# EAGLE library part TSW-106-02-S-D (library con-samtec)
THROUGH-HOLE .025" SQ POST HEADER Source: Samtec TSW.pdf
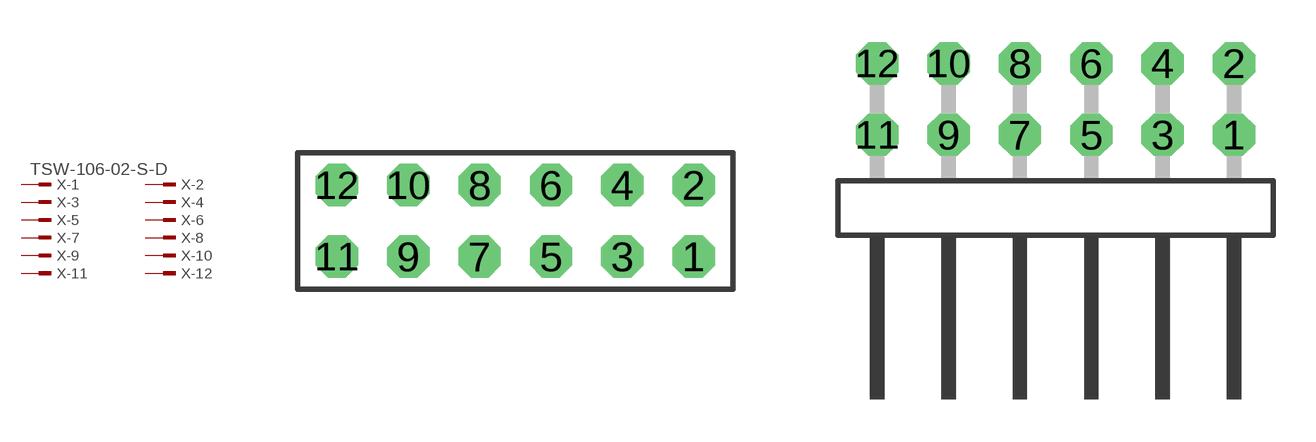
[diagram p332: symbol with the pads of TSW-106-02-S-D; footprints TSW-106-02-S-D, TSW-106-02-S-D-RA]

Designator prefix X; gates -1=MPINV -2=MPIN -3=MPIN -4=MPIN -5=MPIN -6=MPIN -7=MPIN -8=MPIN -9=MPIN -10=MPIN -11=MPIN -12=MPIN

## TSW-106-02-S-D (OC_FARNELL: unknown; OC_NEWARK: unknown)  [TSW-106-02-S-D]
1  -1:1  pas
2  -2:1  pas
3  -3:1  pas
4  -4:1  pas
5  -5:1  pas
6  -6:1  pas
7  -7:1  pas
8  -8:1  pas
9  -9:1  pas
10  -10:1  pas
11  -11:1  pas
12  -12:1  pas

## TSW-106-02-S-D-RA (OC_FARNELL: unknown; OC_NEWARK: unknown)  [TSW-106-02-S-D-RA]
Pads as for TSW-106-02-S-D

## Footprint TSW-106-02-S-D (pad centres in mm)
THROUGH-HOLE .025" SQ POST HEADER Source: Samtec TSW.pdf
drill 1 pad 1.5 octagon: 1 6.35,-1.27; 2 6.35,1.27; 3 3.81,-1.27; 4 3.81,1.27; 5 1.27,-1.27; 6 1.27,1.27; 7 -1.27,-1.27; 8 -1.27,1.27; 9 -3.81,-1.27; 10 -3.81,1.27; 11 -6.35,-1.27; 12 -6.35,1.27

## Footprint TSW-106-02-S-D-RA (pad centres in mm)
THROUGH-HOLE .025" SQ POST HEADER Source: Samtec TSW.pdf
drill 1 pad 1.5 octagon: 1 6.35,1.524; 2 6.35,4.064; 3 3.81,1.524; 4 3.81,4.064; 5 1.27,1.524; 6 1.27,4.064; 7 -1.27,1.524; 8 -1.27,4.064; 9 -3.81,1.524; 10 -3.81,4.064; 11 -6.35,1.524; 12 -6.35,4.064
